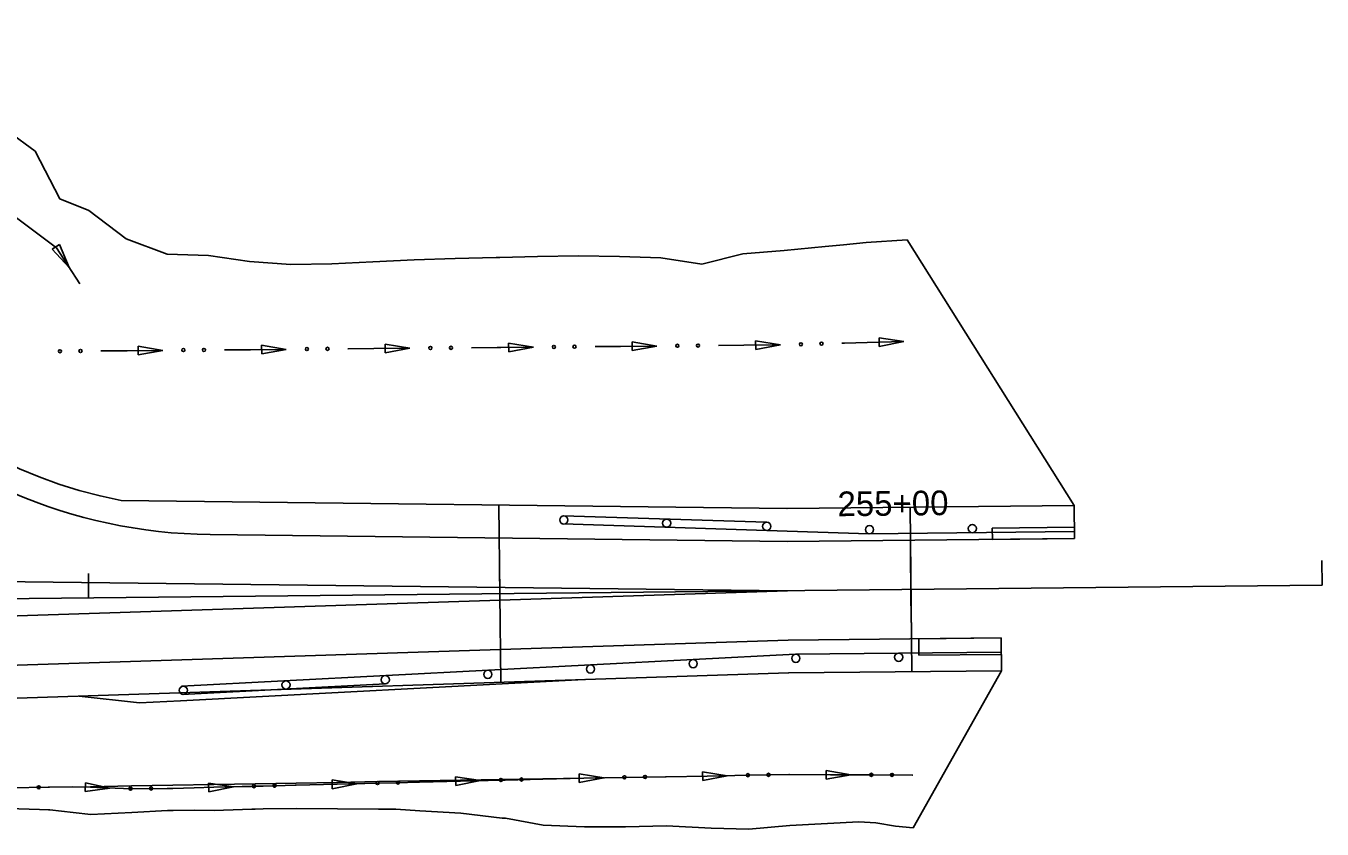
# Model space of a CAD drawing. Extents: x 1611108 to 1749517, y 619561 to 797725.
# Drawn here: x 1714103.5 to 1714418.7, y 759209.9 to 759405.3 of the extents above; entities that cross this region are included whole.
import ezdxf

# ---------------------------------------------------------------- set-up
doc = ezdxf.new("R2010")
doc.units = 0
for name, color, linetype in [('Level 8', 7, 'Continuous'), ('R_Ditch', 7, 'Continuous'), ('R_Guardrail', 7, 'Continuous'), ('R_Horz Alg', 7, 'Continuous'), ('R_Horz Alg Stationing', 7, 'Continuous'), ('R_Proposed Const Limits', 7, 'Continuous'), ('R_Proposed Road', 7, 'Continuous'), ('R_Proposed_SHLDR', 7, 'Continuous'), ('R_Striping', 7, 'Continuous')]:
    doc.layers.add(name, color=color, linetype=linetype)

msp = doc.modelspace()

# ---------------------------------------------------------------- linework, layer by layer
at = {"layer": 'Level 8'}
for p, q in [((1714338.48, 759283.13), (1714358.48, 759283.34)), ((1714338.51, 759280.38), (1714338.48, 759283.13)), ((1714358.48, 759283.34), (1714358.51, 759280.59)), ((1714338.51, 759280.38), (1714358.51, 759280.59)), ((1714320.63, 759256.2), (1714340.63, 759256.4)), ((1714320.67, 759252.2), (1714320.63, 759256.2)), ((1714340.67, 759252.4), (1714340.63, 759256.4)), ((1714320.67, 759252.2), (1714340.67, 759252.4))]:
    msp.add_line(p, q, dxfattribs=at)
at = {"layer": 'R_Ditch'}
for p, q in [((1714111.61, 759352.12), (1714109.84, 759350.97)), ((1714113.99, 759346.51), (1714111.61, 759352.12)), ((1714109.84, 759350.97), (1714113.99, 759346.51)), ((1714316.98, 759328.55), (1714310.95, 759329.43)), ((1714310.95, 759329.43), (1714311.01, 759327.32)), ((1714136.77, 759326.35), (1714130.76, 759327.36)), ((1714130.76, 759327.36), (1714130.78, 759325.24)), ((1714130.78, 759325.24), (1714136.77, 759326.35)), ((1714166.8, 759326.6), (1714160.79, 759327.61)), ((1714160.79, 759327.61), (1714160.81, 759325.5)), ((1714160.81, 759325.5), (1714166.8, 759326.6)), ((1714196.84, 759326.86), (1714190.83, 759327.87)), ((1714190.83, 759327.87), (1714190.85, 759325.75)), ((1714190.85, 759325.75), (1714196.84, 759326.86)), ((1714226.88, 759327.12), (1714220.87, 759328.12)), ((1714220.87, 759328.12), (1714220.89, 759326.01)), ((1714220.89, 759326.01), (1714226.88, 759327.12)), ((1714256.91, 759327.4), (1714250.9, 759328.4)), ((1714250.9, 759328.4), (1714250.92, 759326.29)), ((1714250.92, 759326.29), (1714256.91, 759327.4)), ((1714286.95, 759327.68), (1714280.94, 759328.68)), ((1714280.94, 759328.68), (1714280.96, 759326.56)), ((1714280.96, 759326.56), (1714286.95, 759327.68)), ((1714311.01, 759327.32), (1714316.98, 759328.55)), ((1714213.99, 759221.67), (1714207.97, 759222.58)), ((1714207.97, 759222.58), (1714208.02, 759220.46)), ((1714244.02, 759222.37), (1714238, 759223.33)), ((1714238, 759223.33), (1714238.04, 759221.21)), ((1714238.04, 759221.21), (1714244.02, 759222.37)), ((1714274.06, 759222.88), (1714268.04, 759223.84)), ((1714268.04, 759223.84), (1714268.07, 759221.72)), ((1714268.07, 759221.72), (1714274.06, 759222.88)), ((1714298.1, 759224.16), (1714298.09, 759222.04)), ((1714298.09, 759222.04), (1714304.09, 759223.07)), ((1714304.09, 759223.07), (1714298.1, 759224.16)), ((1714117.95, 759221.17), (1714117.87, 759219.05)), ((1714117.87, 759219.05), (1714123.91, 759219.88)), ((1714123.91, 759219.88), (1714117.95, 759221.17)), ((1714153.93, 759220.17), (1714147.91, 759221.08)), ((1714147.91, 759221.08), (1714147.96, 759218.96)), ((1714147.96, 759218.96), (1714153.93, 759220.17)), ((1714183.96, 759220.92), (1714177.94, 759221.83)), ((1714177.94, 759221.83), (1714177.99, 759219.71)), ((1714177.99, 759219.71), (1714183.96, 759220.92)), ((1714208.02, 759220.46), (1714213.99, 759221.67))]:
    msp.add_line(p, q, dxfattribs=at)
for points in [[(1714098.95, 759360.33), (1714110.88, 759351.31), (1714116.59, 759342.51)], [(1714103.47, 759356.91), (1714110.88, 759351.31), (1714113.99, 759346.51)], [(1714121.73, 759326.22), (1714121.77, 759326.22)], [(1714121.77, 759326.22), (1714128.1, 759326.27), (1714136.77, 759326.35)], [(1714151.77, 759326.48), (1714151.8, 759326.48)], [(1714151.8, 759326.48), (1714158.1, 759326.53), (1714166.8, 759326.6)], [(1714181.8, 759326.73), (1714181.84, 759326.73)], [(1714181.84, 759326.73), (1714188.1, 759326.79), (1714196.84, 759326.86)], [(1714211.84, 759326.99), (1714211.88, 759326.99)], [(1714211.88, 759326.99), (1714218.1, 759327.04), (1714218.95, 759327.05), (1714226.88, 759327.12)], [(1714241.88, 759327.26), (1714241.91, 759327.26)], [(1714241.91, 759327.26), (1714248.1, 759327.32), (1714256.91, 759327.4)], [(1714271.91, 759327.54), (1714271.95, 759327.54)], [(1714271.95, 759327.54), (1714278.09, 759327.59), (1714286.95, 759327.68)], [(1714301.94, 759328.1), (1714301.98, 759328.1)], [(1714301.98, 759328.1), (1714302.55, 759328.12), (1714308.09, 759328.29), (1714316.98, 759328.55)], [(1714099.2, 759219.91), (1714109.2, 759220.06), (1714119.19, 759220.2), (1714129.19, 759220.38), (1714139.19, 759220.55), (1714149.19, 759220.73), (1714159.19, 759220.9), (1714169.19, 759221.08), (1714179.19, 759221.25), (1714189.19, 759221.43), (1714199.18, 759221.6), (1714209.18, 759221.78), (1714219.18, 759221.95), (1714220.03, 759221.97), (1714229.18, 759222.12), (1714239.18, 759222.29), (1714249.18, 759222.46), (1714259.18, 759222.63), (1714269.18, 759222.8), (1714279.17, 759222.97), (1714289.17, 759223.13), (1714299.17, 759223.09), (1714303.64, 759223.08), (1714309.18, 759223.05), (1714319.18, 759223.01)], [(1714108.91, 759220.05), (1714109.2, 759220.06), (1714114.87, 759220.14), (1714119.2, 759220.06), (1714129.2, 759219.68), (1714137.85, 759219.77), (1714139.2, 759219.8), (1714144.38, 759219.93), (1714149.2, 759220.05), (1714156.07, 759220.22), (1714158.35, 759220.28), (1714159.2, 759220.3), (1714161.14, 759220.35), (1714169.19, 759220.55), (1714179.19, 759220.8), (1714189.19, 759221.05), (1714193.4, 759221.16), (1714199.19, 759221.3), (1714209.19, 759221.55), (1714219.18, 759221.8), (1714220.03, 759221.82), (1714229.18, 759222.04), (1714239.18, 759222.29), (1714249.18, 759222.46), (1714259.18, 759222.63), (1714269.18, 759222.8), (1714279.17, 759222.97), (1714289.17, 759223.13), (1714299.17, 759223.09), (1714303.64, 759223.08), (1714309.18, 759223.05), (1714319.18, 759223.01)], [(1714229.03, 759222.04), (1714229.18, 759222.04), (1714239.18, 759222.29), (1714244.02, 759222.37)], [(1714259.02, 759222.63), (1714259.06, 759222.63)], [(1714259.06, 759222.63), (1714259.18, 759222.63), (1714269.18, 759222.8), (1714274.06, 759222.88)], [(1714289.05, 759223.13), (1714289.09, 759223.13)], [(1714289.09, 759223.13), (1714289.17, 759223.13), (1714299.17, 759223.09), (1714303.64, 759223.08), (1714304.09, 759223.07)], [(1714319.09, 759223.01), (1714319.13, 759223.01)], [(1714319.13, 759223.01), (1714319.18, 759223.01)], [(1714108.91, 759220.05), (1714109.2, 759220.06), (1714114.87, 759220.14), (1714119.2, 759220.06), (1714123.91, 759219.88)], [(1714138.9, 759219.79), (1714138.94, 759219.79)], [(1714138.94, 759219.79), (1714139.2, 759219.8), (1714144.38, 759219.93), (1714149.2, 759220.05), (1714153.93, 759220.17)], [(1714168.93, 759220.54), (1714168.97, 759220.54)], [(1714168.97, 759220.54), (1714169.19, 759220.55), (1714179.19, 759220.8), (1714183.96, 759220.92)], [(1714198.96, 759221.3), (1714199, 759221.3)], [(1714199, 759221.3), (1714199.19, 759221.3), (1714209.19, 759221.55), (1714213.99, 759221.67)], [(1714228.99, 759222.04), (1714229.02, 759222.04)]]:
    msp.add_lwpolyline(points, dxfattribs=at)
for centre in [(1714111.74, 759326.15), (1714116.75, 759326.21), (1714141.77, 759326.43), (1714146.78, 759326.47), (1714171.81, 759326.68), (1714176.82, 759326.73), (1714201.85, 759326.94), (1714206.86, 759326.98), (1714231.88, 759327.2), (1714236.89, 759327.25), (1714261.92, 759327.48), (1714266.93, 759327.53), (1714291.95, 759327.84), (1714296.96, 759327.99), (1714219, 759221.83), (1714224, 759221.95), (1714249.03, 759222.49), (1714254.04, 759222.58), (1714279.06, 759223), (1714284.07, 759223.08), (1714309.1, 759223.09), (1714314.11, 759223.07), (1714106.58, 759220.06), (1714128.91, 759219.73), (1714133.92, 759219.76), (1714158.94, 759220.33), (1714163.95, 759220.46), (1714188.97, 759221.08), (1714193.97, 759221.21)]:
    msp.add_circle(centre, 0.375, dxfattribs=at)
at = {"layer": 'R_Guardrail'}
for p, q in [((1714234.12, 759286.11), (1714283.57, 759284.54)), ((1714234.06, 759284.12), (1714308.49, 759281.74)), ((1714358.49, 759282.26), (1714308.49, 759281.74)), ((1714290.66, 759252.44), (1714141.33, 759244.64)), ((1714340.66, 759252.96), (1714290.66, 759252.44)), ((1714239.27, 759246.25), (1714141.05, 759241.12)), ((1714190.93, 759245.23), (1714141.44, 759242.64)), ((1714116.44, 759242.25), (1714131.06, 759240.59)), ((1714141.05, 759241.12), (1714131.06, 759240.59))]:
    msp.add_line(p, q, dxfattribs=at)
for centre in [(1714234.3, 759285.1), (1714259.29, 759284.31), (1714283.65, 759283.54), (1714308.63, 759282.74), (1714333.63, 759283), (1714265.75, 759250.14), (1714290.72, 759251.44), (1714315.72, 759251.7), (1714215.82, 759247.53), (1714240.79, 759248.83), (1714141.76, 759243.66), (1714166.72, 759244.96), (1714190.86, 759246.22)]:
    msp.add_circle(centre, 1, dxfattribs=at)
at = {"layer": 'R_Horz Alg'}
msp.add_line((1712918.78, 759253.72), (1714418.7, 759269.21), dxfattribs=at)
at = {"layer": 'R_Horz Alg Stationing'}
for points in [[(1714318.63, 759276.18), (1714318.79, 759260.18)], [(1714218.65, 759273.15), (1714218.72, 759267.15)], [(1714418.64, 759275.21), (1714418.7, 759269.21)], [(1714118.66, 759272.11), (1714118.72, 759266.11)]]:
    msp.add_lwpolyline(points, dxfattribs=at)
at = {"layer": 'R_Proposed Const Limits'}
for p, q in [((1714358.42, 759288.59), (1714317.83, 759353.26)), ((1714319.26, 759210.17), (1714340.74, 759248.41))]:
    msp.add_line(p, q, dxfattribs=at)
for points in [[(1714118.77, 759360.37), (1714111.71, 759363.25), (1714105.7, 759374.84), (1714099.3, 759379.56)], [(1714118.77, 759360.37), (1714127.85, 759353.5), (1714137.86, 759349.73), (1714147.86, 759349.41), (1714157.88, 759347.99), (1714167.89, 759347.25), (1714177.88, 759347.41), (1714187.88, 759347.92), (1714197.88, 759348.42), (1714207.87, 759348.74), (1714217.87, 759348.97), (1714218.72, 759348.98), (1714227.87, 759349.16), (1714237.87, 759349.39), (1714247.87, 759349.16), (1714257.87, 759348.86), (1714267.89, 759347.34), (1714277.86, 759349.85), (1714287.86, 759350.64), (1714297.85, 759351.64), (1714302.3, 759352.06), (1714307.84, 759352.59), (1714317.83, 759353.26)], [(1714099.25, 759214.88), (1714109.25, 759214.55)], [(1714319.26, 759210.17), (1714314.99, 759210.59), (1714310.14, 759211.43), (1714306.07, 759211.63), (1714289.3, 759210.76), (1714279.31, 759209.89), (1714270.15, 759210.12), (1714259.3, 759210.69), (1714249.3, 759210.46), (1714239.32, 759210.41), (1714229.3, 759210.81), (1714220.13, 759212.52), (1714219.28, 759212.56), (1714209.27, 759213.74), (1714199.26, 759214.34), (1714193.46, 759214.72), (1714189.25, 759214.77), (1714179.25, 759214.85), (1714169.25, 759214.93), (1714161.2, 759214.82), (1714159.25, 759214.74), (1714158.4, 759214.71), (1714156.13, 759214.63), (1714149.26, 759214.38), (1714144.44, 759214.49), (1714139.26, 759214.42), (1714137.91, 759214.4), (1714129.26, 759213.92), (1714119.27, 759213.4), (1714114.93, 759213.95), (1714109.25, 759214.55), (1714108.94, 759214.56)]]:
    msp.add_lwpolyline(points, dxfattribs=at)
at = {"layer": 'R_Proposed Road'}
for p, q in [((1714288.51, 759287.87), (1714126.64, 759289.8)), ((1714218.49, 759288.71), (1714218.94, 759245.59)), ((1714288.64, 759287.87), (1714358.42, 759288.59)), ((1714358.51, 759280.59), (1714358.42, 759288.59)), ((1714318.5, 759288.18), (1714318.92, 759248.18)), ((1714288.59, 759279.87), (1714148.29, 759281.54)), ((1714288.59, 759279.87), (1714358.51, 759280.59)), ((1714288.84, 759255.87), (1714018.91, 759247.08)), ((1714288.84, 759255.87), (1714340.63, 759256.4)), ((1714340.63, 759256.4), (1714340.74, 759248.41)), ((1714288.92, 759247.87), (1714018.99, 759239.08)), ((1714289.05, 759247.87), (1714340.74, 759248.41))]:
    msp.add_line(p, q, dxfattribs=at)
msp.add_arc((1714149.77, 759406.53), 125, 180.5917, 269.3186, dxfattribs=at)
at = {"layer": 'R_Proposed_SHLDR'}
msp.add_arc((1714149.77, 759406.53), 119, 180.5917, 258.7915, dxfattribs=at)
at = {"layer": 'R_Striping'}
for q in [(1714031.93, 759270.92), (1714032.04, 759259.51)]:
    msp.add_line((1714288.71, 759267.87), q, dxfattribs=at)

# ---------------------------------------------------------------- texts
at = {"layer": 'R_Horz Alg Stationing'}
msp.add_text('255+00', height=6, rotation=0.5917, dxfattribs=at).set_placement((1714300.88, 759286))

doc.saveas('drawing.dxf')
